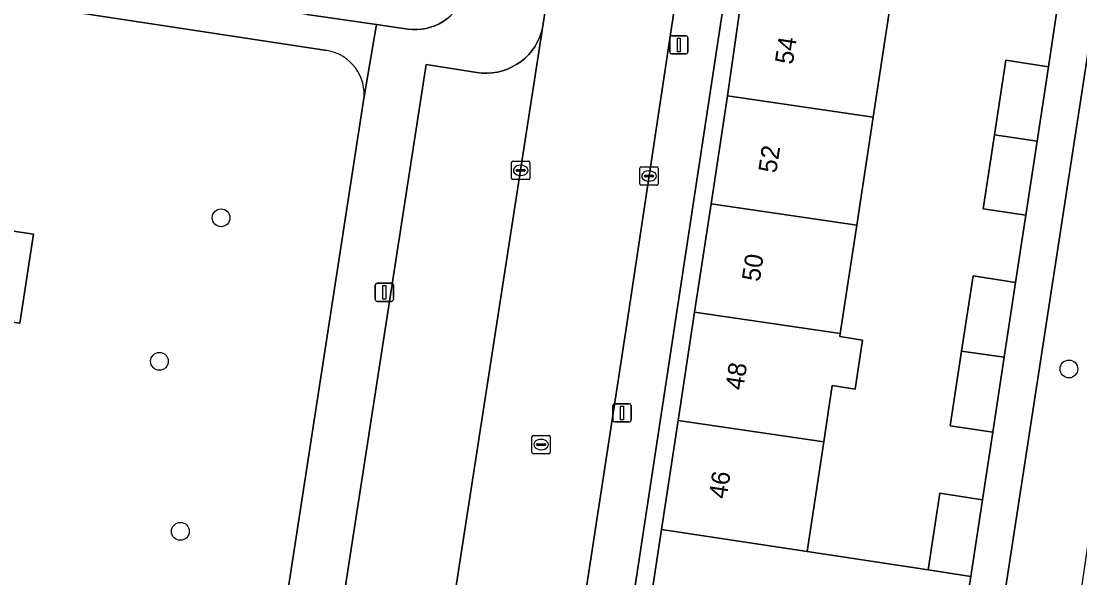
# Model space of a CAD drawing. Extents: x 161084 to 161928, y 385354 to 386522.
# Drawn here: x 161719.8 to 161777.8, y 385574.5 to 385605.1 of the extents above; entities that cross this region are included whole.
import ezdxf

# ---------------------------------------------------------------- set-up
doc = ezdxf.new("R2010")
doc.units = 0
for name, color, linetype in [('IMGEO_Boom', 7, 'Continuous'), ('IMGEO_Erf', 7, 'Continuous'), ('IMGEO_Groenvoorziening', 7, 'Continuous'), ('IMGEO_Kolk', 7, 'Continuous'), ('IMGEO_Lichtmast', 7, 'Continuous'), ('IMGEO_Pand', 7, 'Continuous'), ('IMGEO_Pand_nummerreeks', 7, 'Continuous'), ('IMGEO_Parkeervlak_open', 7, 'Continuous'), ('IMGEO_Rijbaan_lokaal_open', 7, 'Continuous'), ('IMGEO_Rioolput', 7, 'Continuous'), ('IMGEO_Voetpad_open', 7, 'Continuous')]:
    doc.layers.add(name, color=color, linetype=linetype)

msp = doc.modelspace()

# ---------------------------------------------------------------- linework, layer by layer
at = {"layer": 'IMGEO_Boom'}
for centre in [(161730.753, 385594.276), (161727.371, 385586.398), (161777.246, 385585.98), (161728.521, 385577.065)]:
    msp.add_circle(centre, 0.489, dxfattribs=at)
at = {"layer": 'IMGEO_Erf'}
msp.add_lwpolyline([(161763, 385630.627), (161762.136, 385630.764), (161758.437, 385606.815), (161749.416, 385547.492), (161750.362, 385547.348), (161751.288, 385553.43), (161752.196, 385559.391), (161753.098, 385565.313), (161754.003, 385571.254), (161754.905, 385577.176), (161755.814, 385583.147), (161756.72, 385589.098), (161757.625, 385595.04), (161758.527, 385600.961), (161759.367, 385606.876), (161759.871, 385610.168), (161760.279, 385612.833), (161761.186, 385618.764), (161762.093, 385624.695)], close=True, dxfattribs=at)
msp.add_lwpolyline([(161767.411, 385605.677), (161766.515, 385599.795), (161765.613, 385593.874), (161764.708, 385587.932), (161764.681, 385587.754), (161765.926, 385587.564), (161765.516, 385584.876), (161764.271, 385585.066), (161763.801, 385581.981), (161762.883, 385575.96), (161769.534, 385574.946), (161770.175, 385579.16), (161772.508, 385578.805), (161773.07, 385582.502), (161770.737, 385582.857), (161771.361, 385586.961), (161771.987, 385591.083), (161774.32, 385590.728), (161774.881, 385594.416), (161772.548, 385594.771), (161773.164, 385598.824), (161773.786, 385602.917), (161776.119, 385602.562), (161776.737, 385606.625)], dxfattribs=at)
at = {"layer": 'IMGEO_Groenvoorziening'}
for points in [[(161805.27, 385620.775), (161789.899, 385624.833), (161790.31, 385626.472), (161786.741, 385626.995), (161782.033, 385627.684), (161773.386, 385571.42), (161773.877, 385571.344), (161777.482, 385570.79), (161778.873, 385580.217), (161792.543, 385577.832), (161794.539, 385584.566), (161796.185, 385590.122), (161797.834, 385595.686)], [(161743.925, 385606.175), (161744.027, 385606.407), (161744.108, 385606.647), (161744.167, 385606.893), (161744.173, 385606.922), (161744.491, 385609.053), (161736.201, 385610.325), (161735.459, 385605.43), (161739.275, 385604.876), (161740.99, 385604.627), (161741.242, 385604.603), (161741.495, 385604.601), (161741.748, 385604.622), (161741.997, 385604.665), (161742.242, 385604.731), (161742.479, 385604.818), (161742.708, 385604.926), (161742.927, 385605.054), (161743.133, 385605.201), (161743.325, 385605.366), (161743.502, 385605.547), (161743.662, 385605.743), (161743.803, 385605.953)], [(161719.717, 385588.484), (161720.467, 385593.373), (161715.569, 385594.099), (161714.819, 385589.209)], [(161719.717, 385588.484), (161714.819, 385589.209), (161715.569, 385594.099), (161720.467, 385593.373)]]:
    msp.add_lwpolyline(points, close=True, dxfattribs=at)
for points in [[(161736.552, 385603.449), (161714.658, 385606.809), (161709.299, 385571.47), (161731.363, 385568.084)], [(161733.802, 385569.867), (161738.568, 385600.711)]]:
    msp.add_lwpolyline(points, dxfattribs=at)
msp.add_arc((161736.184, 385601.067), 2.41, 351.50906, 81.21966, dxfattribs=at)
at = {"layer": 'IMGEO_Kolk'}
for p, q in [((161746.682, 385596.45), (161746.682, 385597.302)), ((161746.757, 385597.376), (161747.609, 385597.376)), ((161747.17, 385597.156), (161747.195, 385597.156)), ((161747.683, 385597.302), (161747.683, 385596.45)), ((161753.794, 385597.065), (161754.646, 385597.065)), ((161746.941, 385596.87), (161746.941, 385596.882)), ((161747.379, 385596.833), (161746.981, 385596.833)), ((161746.984, 385596.919), (161747.382, 385596.919)), ((161747.193, 385596.596), (161747.168, 385596.596)), ((161747.425, 385596.882), (161747.425, 385596.87)), ((161753.719, 385596.139), (161753.719, 385596.991)), ((161753.978, 385596.559), (161753.978, 385596.571)), ((161754.416, 385596.522), (161754.018, 385596.522)), ((161754.021, 385596.608), (161754.419, 385596.608)), ((161754.207, 385596.845), (161754.232, 385596.845)), ((161754.462, 385596.571), (161754.462, 385596.559)), ((161754.72, 385596.991), (161754.72, 385596.139)), ((161747.609, 385596.376), (161746.757, 385596.376)), ((161754.646, 385596.065), (161753.794, 385596.065)), ((161754.23, 385596.285), (161754.205, 385596.285))]:
    msp.add_line(p, q, dxfattribs=at)
for points in [[(161746.682, 385596.45), (161746.682, 385597.302)], [(161746.757, 385597.376), (161747.609, 385597.376)], [(161747.683, 385597.302), (161747.683, 385596.45)], [(161753.794, 385597.065), (161754.646, 385597.065)], [(161753.719, 385596.139), (161753.719, 385596.991)], [(161754.72, 385596.991), (161754.72, 385596.139)], [(161747.609, 385596.376), (161746.757, 385596.376)], [(161754.646, 385596.065), (161753.794, 385596.065)]]:
    msp.add_lwpolyline(points, dxfattribs=at)
for centre, radius, start, end in [((161746.759, 385597.3), 0.0765, 91.55205, 178.44795), ((161746.759, 385597.3), 0.0765, 91.55205, 178.44795), ((161747.607, 385597.3), 0.0765, 1.55205, 88.44795), ((161747.607, 385597.3), 0.0765, 1.55205, 88.44795), ((161753.796, 385596.989), 0.0765, 91.55205, 178.44795), ((161753.796, 385596.989), 0.0765, 91.55205, 178.44795), ((161754.644, 385596.989), 0.0765, 1.55205, 88.44795), ((161754.644, 385596.989), 0.0765, 1.55205, 88.44795), ((161746.981, 385596.879), 0.0403, 85.87752, 175.75265), ((161746.978, 385596.869), 0.0366, 178.93798, 274.71019), ((161747.382, 385596.876), 0.043, 264.86636, 352.45326), ((161747.386, 385596.881), 0.0386, 1.73085, 96.63898), ((161754.018, 385596.568), 0.0403, 85.87752, 175.75265), ((161754.015, 385596.558), 0.0366, 178.93798, 274.71019), ((161754.419, 385596.565), 0.043, 264.86636, 352.45326), ((161754.423, 385596.57), 0.0386, 1.73085, 96.63898), ((161746.759, 385596.452), 0.0765, 181.55205, 268.44795), ((161746.759, 385596.452), 0.0765, 181.55205, 268.44795), ((161747.607, 385596.452), 0.0765, 271.55205, 358.44795), ((161747.607, 385596.452), 0.0765, 271.55205, 358.44795), ((161753.796, 385596.141), 0.0765, 181.55205, 268.44795), ((161753.796, 385596.141), 0.0765, 181.55205, 268.44795), ((161754.644, 385596.141), 0.0765, 271.55205, 358.44795), ((161754.644, 385596.141), 0.0765, 271.55205, 358.44795)]:
    msp.add_arc(centre, radius, start, end, dxfattribs=at)
for centre, major_axis, ratio, start_param, end_param in [((161747.169, 385596.876), (-0.387, 0.002), 0.722429, 4.712389, 7.853982), ((161747.194, 385596.876), (-0.39, 0.002), 0.717154, 1.570796, 4.712389), ((161754.206, 385596.565), (-0.387, 0.002), 0.722429, 4.712389, 7.853982), ((161754.231, 385596.565), (-0.39, 0.002), 0.717154, 1.570796, 4.712389)]:
    msp.add_ellipse(centre, major_axis=major_axis, ratio=ratio, start_param=start_param, end_param=end_param, dxfattribs=at)
at = {"layer": 'IMGEO_Lichtmast'}
for p, q in [((161755.353, 385603.366), (161755.353, 385604.166)), ((161755.353, 385604.166), (161755.353, 385603.366)), ((161755.453, 385604.266), (161756.243, 385604.266)), ((161756.243, 385604.266), (161755.453, 385604.266)), ((161756.343, 385604.166), (161756.343, 385603.366)), ((161756.343, 385603.366), (161756.343, 385604.166)), ((161756.243, 385603.266), (161755.453, 385603.266)), ((161755.453, 385603.266), (161756.243, 385603.266)), ((161739.31, 385590.689), (161740.1, 385590.689)), ((161740.1, 385590.689), (161739.31, 385590.689)), ((161739.21, 385589.789), (161739.21, 385590.589)), ((161739.21, 385590.589), (161739.21, 385589.789)), ((161740.2, 385590.589), (161740.2, 385589.789)), ((161740.2, 385589.789), (161740.2, 385590.589)), ((161740.1, 385589.689), (161739.31, 385589.689)), ((161739.31, 385589.689), (161740.1, 385589.689)), ((161752.243, 385583.169), (161752.243, 385583.969)), ((161752.243, 385583.969), (161752.243, 385583.169)), ((161752.343, 385584.069), (161753.133, 385584.069)), ((161753.133, 385584.069), (161752.343, 385584.069)), ((161753.233, 385583.969), (161753.233, 385583.169)), ((161753.233, 385583.169), (161753.233, 385583.969)), ((161753.133, 385583.069), (161752.343, 385583.069)), ((161752.343, 385583.069), (161753.133, 385583.069))]:
    msp.add_line(p, q, dxfattribs=at)
for points in [[(161755.773, 385604.141), (161755.923, 385604.141), (161755.923, 385603.391), (161755.773, 385603.391), (161755.773, 385604.141)], [(161739.63, 385590.564), (161739.78, 385590.564), (161739.78, 385589.814), (161739.63, 385589.814), (161739.63, 385590.564)], [(161752.663, 385583.944), (161752.813, 385583.944), (161752.813, 385583.194), (161752.663, 385583.194), (161752.663, 385583.944)]]:
    msp.add_lwpolyline(points, dxfattribs=at)
for centre, start, end in [((161755.453, 385604.166), 90, 180), ((161755.453, 385604.166), 90, 180), ((161756.243, 385604.166), 0, 90), ((161756.243, 385604.166), 360, 90), ((161755.453, 385603.366), 180, 270), ((161755.453, 385603.366), 180, 270), ((161756.243, 385603.366), 270, 0), ((161756.243, 385603.366), 270, 0), ((161739.31, 385590.589), 90, 180), ((161739.31, 385590.589), 90, 180), ((161740.1, 385590.589), 0, 90), ((161740.1, 385590.589), 360, 90), ((161739.31, 385589.789), 180, 270), ((161739.31, 385589.789), 180, 270), ((161740.1, 385589.789), 270, 0), ((161740.1, 385589.789), 270, 0), ((161752.343, 385583.969), 90, 180), ((161752.343, 385583.969), 90, 180), ((161753.133, 385583.969), 0, 90), ((161753.133, 385583.969), 360, 90), ((161752.343, 385583.169), 180, 270), ((161752.343, 385583.169), 180, 270), ((161753.133, 385583.169), 270, 0), ((161753.133, 385583.169), 270, 0)]:
    msp.add_arc(centre, 0.1, start, end, dxfattribs=at)
at = {"layer": 'IMGEO_Pand'}
for points in [[(161766.515, 385599.795), (161767.411, 385605.677), (161759.367, 385606.876), (161758.527, 385600.961)], [(161775.499, 385598.484), (161776.119, 385602.562), (161773.786, 385602.917), (161773.164, 385598.824)], [(161758.527, 385600.961), (161757.625, 385595.04), (161765.613, 385593.874), (161766.515, 385599.795)], [(161773.164, 385598.824), (161772.548, 385594.771), (161774.881, 385594.416), (161775.499, 385598.484)], [(161764.708, 385587.932), (161765.613, 385593.874), (161757.625, 385595.04), (161756.72, 385589.098)], [(161773.696, 385586.62), (161774.32, 385590.728), (161771.987, 385591.083), (161771.361, 385586.961)], [(161764.681, 385587.754), (161764.708, 385587.932), (161756.72, 385589.098), (161755.814, 385583.147), (161763.801, 385581.981), (161764.271, 385585.066), (161765.516, 385584.876), (161765.926, 385587.564)], [(161771.361, 385586.961), (161770.737, 385582.857), (161773.07, 385582.502), (161773.696, 385586.62)], [(161755.814, 385583.147), (161754.905, 385577.176), (161762.883, 385575.96), (161763.801, 385581.981)], [(161771.867, 385574.591), (161772.508, 385578.805), (161770.175, 385579.16), (161769.534, 385574.946)], [(161771.867, 385574.591), (161769.534, 385574.946), (161762.883, 385575.96), (161754.905, 385577.176), (161754.003, 385571.254), (161761.982, 385570.039), (161762.432, 385572.994), (161767.403, 385572.238), (161766.923, 385569.179), (161770.92, 385568.571), (161771.416, 385571.723)]]:
    msp.add_lwpolyline(points, close=True, dxfattribs=at)
at = {"layer": 'IMGEO_Parkeervlak_open'}
msp.add_lwpolyline([(161742.027, 385563.68), (161748.381, 385604.68), (161748.327, 385604.479), (161748.232, 385604.209), (161748.113, 385603.948), (161747.971, 385603.7), (161747.807, 385603.465), (161747.624, 385603.245), (161747.421, 385603.043), (161747.201, 385602.86), (161746.966, 385602.697), (161746.717, 385602.556), (161746.456, 385602.438), (161746.186, 385602.343), (161745.909, 385602.273), (161745.626, 385602.228), (161745.341, 385602.208), (161745.054, 385602.214), (161744.77, 385602.246), (161741.992, 385602.681), (161736.551, 385567.468)], dxfattribs=at)
at = {"layer": 'IMGEO_Rijbaan_lokaal_open'}
for points in [[(161752.959, 385588.197), (161755.485, 385604.964), (161758.804, 385627.019), (161759.266, 385629.984)], [(161749.647, 385612.852), (161748.381, 385604.68), (161742.027, 385563.68), (161739.541, 385547.634), (161739.451, 385547.152), (161739.259, 385546.423), (161739.002, 385545.714), (161738.683, 385545.03), (161738.304, 385544.378), (161737.868, 385543.762), (161737.379, 385543.188), (161731.192, 385536.55), (161730.397, 385535.617), (161729.689, 385534.617), (161729.073, 385533.557), (161728.554, 385532.447), (161728.136, 385531.295), (161727.823, 385530.11), (161727.669, 385529.274), (161723.237, 385500), (161713.061, 385433.189)], [(161719.723, 385430.887), (161719.914, 385431.913), (161720.36, 385434.843), (161730.285, 385500), (161733.96, 385523.829), (161734.945, 385529.848), (161735.034, 385530.378), (161735.175, 385530.918), (161735.362, 385531.442), (161735.597, 385531.948), (161735.875, 385532.431), (161736.195, 385532.887), (161736.555, 385533.313), (161736.762, 385533.508), (161746.133, 385543.607), (161752.959, 385588.197)]]:
    msp.add_lwpolyline(points, dxfattribs=at)
at = {"layer": 'IMGEO_Rioolput'}
for p, q in [((161747.8, 385581.403), (161747.8, 385582.255)), ((161747.875, 385582.329), (161748.727, 385582.329)), ((161748.288, 385582.109), (161748.313, 385582.109)), ((161748.801, 385582.255), (161748.801, 385581.403)), ((161748.059, 385581.823), (161748.059, 385581.835)), ((161748.497, 385581.786), (161748.099, 385581.786)), ((161748.102, 385581.872), (161748.5, 385581.872)), ((161748.311, 385581.549), (161748.286, 385581.549)), ((161748.543, 385581.835), (161748.543, 385581.823)), ((161748.727, 385581.329), (161747.875, 385581.329))]:
    msp.add_line(p, q, dxfattribs=at)
for points in [[(161747.8, 385581.403), (161747.8, 385582.255)], [(161747.875, 385582.329), (161748.727, 385582.329)], [(161748.801, 385582.255), (161748.801, 385581.403)], [(161748.727, 385581.329), (161747.875, 385581.329)]]:
    msp.add_lwpolyline(points, dxfattribs=at)
for centre, radius, start, end in [((161747.877, 385582.253), 0.0765, 91.55205, 178.44795), ((161747.877, 385582.253), 0.0765, 91.55205, 178.44795), ((161748.725, 385582.253), 0.0765, 1.55205, 88.44795), ((161748.725, 385582.253), 0.0765, 1.55205, 88.44795), ((161747.877, 385581.405), 0.0765, 181.55205, 268.44795), ((161747.877, 385581.405), 0.0765, 181.55205, 268.44795), ((161748.099, 385581.832), 0.0403, 85.87752, 175.75265), ((161748.096, 385581.822), 0.0366, 178.93798, 274.71019), ((161748.5, 385581.829), 0.043, 264.86636, 352.45326), ((161748.504, 385581.834), 0.0386, 1.73085, 96.63898), ((161748.725, 385581.405), 0.0765, 271.55205, 358.44795), ((161748.725, 385581.405), 0.0765, 271.55205, 358.44795)]:
    msp.add_arc(centre, radius, start, end, dxfattribs=at)
for centre, major_axis, ratio, start_param, end_param in [((161748.287, 385581.829), (-0.387, 0.002), 0.722429, 4.712389, 7.853982), ((161748.312, 385581.829), (-0.39, 0.002), 0.717154, 1.570796, 4.712389)]:
    msp.add_ellipse(centre, major_axis=major_axis, ratio=ratio, start_param=start_param, end_param=end_param, dxfattribs=at)
at = {"layer": 'IMGEO_Voetpad_open'}
for points in [[(161759.266, 385629.984), (161758.804, 385627.019), (161755.485, 385604.964), (161752.959, 385588.197), (161746.133, 385543.607), (161748.748, 385543.117), (161749.416, 385547.492), (161758.437, 385606.815)], [(161721.233, 385607.593), (161722.032, 385612.497), (161721.851, 385612.525), (161722.045, 385613.788), (161719.155, 385614.231), (161718.961, 385612.968), (161720.881, 385612.673), (161720.134, 385607.742), (161715.193, 385608.513), (161701.288, 385610.683), (161700.995, 385608.885), (161704.848, 385608.336), (161704.883, 385608.326), (161713.072, 385607.113), (161714.658, 385606.809), (161736.552, 385603.449)], [(161736.312, 385565.923), (161736.551, 385567.468), (161741.992, 385602.681), (161744.77, 385602.246), (161745.054, 385602.214), (161745.341, 385602.208), (161745.626, 385602.228), (161745.909, 385602.273), (161746.186, 385602.343), (161746.456, 385602.438), (161746.717, 385602.556), (161746.966, 385602.697), (161747.201, 385602.86), (161747.421, 385603.043), (161747.624, 385603.245), (161747.807, 385603.465), (161747.971, 385603.7), (161748.113, 385603.948), (161748.232, 385604.209), (161748.327, 385604.479), (161748.381, 385604.68), (161749.647, 385612.852)], [(161738.568, 385600.711), (161739.275, 385604.876), (161735.459, 385605.43), (161731.425, 385606.015), (161730.197, 385606.186), (161721.233, 385607.593)], [(161743.133, 385605.201), (161742.927, 385605.054), (161742.708, 385604.926), (161742.479, 385604.818), (161742.242, 385604.731), (161741.997, 385604.665), (161741.748, 385604.622), (161741.495, 385604.601), (161741.242, 385604.603), (161740.99, 385604.627), (161739.275, 385604.876), (161738.568, 385600.711), (161733.802, 385569.867)]]:
    msp.add_lwpolyline(points, dxfattribs=at)
msp.add_lwpolyline([(161782.033, 385627.684), (161779.887, 385627.999), (161779.086, 385622.106), (161778.471, 385618.075), (161777.843, 385613.902), (161777.287, 385610.242), (161776.737, 385606.625), (161776.119, 385602.562), (161775.499, 385598.484), (161774.881, 385594.416), (161774.32, 385590.728), (161773.696, 385586.62), (161773.07, 385582.502), (161772.508, 385578.805), (161771.867, 385574.591), (161771.416, 385571.723), (161773.386, 385571.42)], close=True, dxfattribs=at)
msp.add_arc((161736.184, 385601.067), 2.41, 351.50906, 81.21966, dxfattribs=at)

# ---------------------------------------------------------------- texts
at = {"layer": 'IMGEO_Pand_nummerreeks'}
for s, rotation, p in [('54', 81.34086, (161762.102, 385602.652)), ('52', 81.34086, (161761.194, 385596.69)), ('50', 81.34086, (161760.288, 385590.736)), ('48', 81.34282, (161759.38, 385584.777)), ('46', 81.34086, (161758.472, 385578.814))]:
    msp.add_text(s, height=1, rotation=rotation, dxfattribs=at).set_placement(p)

doc.saveas('drawing.dxf')
